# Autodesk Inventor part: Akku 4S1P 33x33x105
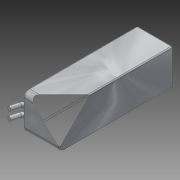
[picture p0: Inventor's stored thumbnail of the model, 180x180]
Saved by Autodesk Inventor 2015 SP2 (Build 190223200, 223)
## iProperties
Created: 2012-08
Part Number: Akku 4S1P 33x33x105
Material: Glas
Document SubType Name: Modeling
Designer: rYan
Mass: 248.871 g
Surface Area: 159.219 cm^2
Volume: 114.161 cm^3
Density: 2.18 g/cm^3
Description: TP1300-4SPR45
Vendor: Thunder Power
Appearance: Klar
Author: rYan
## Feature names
1. Extrusion1
2. Rundung1 [Fillet]
3. Rundung2 [Fillet]
4. Sweeping4
5. Spiegeln3 [Mirror]
## Parameters: d0 = 33 mm, d2 = 105 mm, d3 = 33 mm, d4 = 0, d5 = 5 mm, d26 = 4 mm, d33 = 1 mm, d38 = 75 deg, d39 = 8 mm, d40 = 3 mm, d42 = 4 mm, d43 = 1 mm, d44 = 0, d45 = 0
